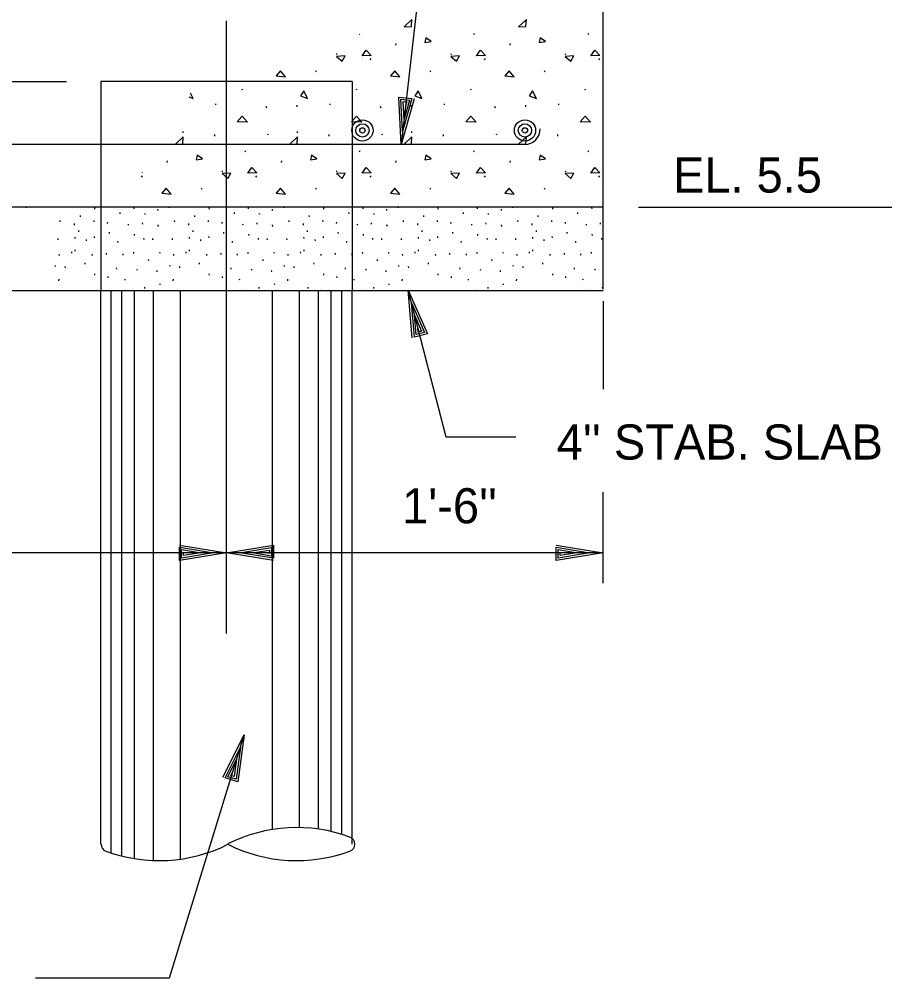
# Model space of a CAD drawing. Extents: x 0 to 320, y -4 to 473.
# Drawn here: x 13.435 to 16.911, y 11.095 to 14.916 of the extents above; entities that cross this region are included whole.
import ezdxf

# ---------------------------------------------------------------- set-up
doc = ezdxf.new("R2010")
doc.units = 0
for name, color, linetype in [('Level 10', 7, 'Continuous'), ('Level 2', 7, 'Continuous'), ('Level 3', 7, 'Continuous'), ('Level 44', 7, 'Continuous'), ('Level 50', 7, 'Continuous')]:
    doc.layers.add(name, color=color, linetype=linetype)

msp = doc.modelspace()

# ---------------------------------------------------------------- linework, layer by layer
at = {"layer": 'Level 10'}
for p, q in [((14.7906, 14.855), (14.7918, 14.8576)), ((15.2461, 14.855), (15.2484, 14.8599)), ((15.7016, 14.855), (15.7039, 14.8599)), ((14.9352, 14.813), (14.9361, 14.819)), ((15.3907, 14.813), (15.3916, 14.819)), ((14.7006, 14.775), (14.701, 14.7796)), ((14.8336, 14.7541), (14.8367, 14.7594)), ((15.1561, 14.775), (15.1565, 14.7796)), ((15.2891, 14.7541), (15.2922, 14.7594)), ((15.6116, 14.775), (15.612, 14.7796)), ((15.7446, 14.7541), (15.7478, 14.7594)), ((14.619, 14.7054), (14.6162, 14.7109)), ((15.0745, 14.7054), (15.0717, 14.7109)), ((15.5301, 14.7054), (15.5272, 14.7109)), ((14.3239, 14.6328), (14.3235, 14.6379)), ((14.7794, 14.6328), (14.779, 14.6379)), ((15.2349, 14.6328), (15.2345, 14.6379)), ((15.6905, 14.6328), (15.6901, 14.6379)), ((14.218, 14.5744), (14.2188, 14.579)), ((14.4209, 14.562), (14.4191, 14.5682)), ((14.5421, 14.567), (14.5421, 14.5732)), ((14.6735, 14.5744), (14.6743, 14.579)), ((14.8764, 14.562), (14.8746, 14.5682)), ((14.9977, 14.567), (14.9977, 14.5732)), ((15.129, 14.5744), (15.1298, 14.579)), ((15.3319, 14.562), (15.3302, 14.5682)), ((15.4532, 14.567), (15.4532, 14.5732)), ((15.5845, 14.5744), (15.5854, 14.579)), ((14.0888, 14.4633), (14.0888, 14.4691)), ((14.2141, 14.4499), (14.2141, 14.4561)), ((14.4271, 14.4541), (14.4254, 14.4586)), ((14.5443, 14.4633), (14.5443, 14.4691)), ((14.6696, 14.4499), (14.6696, 14.4561)), ((14.8827, 14.4541), (14.8809, 14.4586)), ((14.9998, 14.4633), (14.9998, 14.4691)), ((15.1252, 14.4499), (15.1252, 14.4561)), ((15.3382, 14.4541), (15.3364, 14.4586)), ((15.4554, 14.4633), (15.4554, 14.4691)), ((15.5807, 14.4499), (15.5807, 14.4561)), ((14.3351, 14.3874), (14.3373, 14.3923)), ((14.7906, 14.3874), (14.7929, 14.3923)), ((15.2461, 14.3874), (15.2484, 14.3923)), ((15.7016, 14.3874), (15.7039, 14.3923)), ((14.0241, 14.3454), (14.0251, 14.3514)), ((14.4796, 14.3454), (14.4806, 14.3514)), ((14.9352, 14.3454), (14.9361, 14.3514)), ((15.3907, 14.3454), (15.3916, 14.3514)), ((14.2451, 14.3074), (14.2455, 14.312)), ((14.7006, 14.3074), (14.701, 14.312)), ((15.1561, 14.3074), (15.1565, 14.312)), ((15.6116, 14.3074), (15.612, 14.312)), ((13.9226, 14.2865), (13.9257, 14.2918)), ((14.3781, 14.2865), (14.3812, 14.2918)), ((14.8336, 14.2865), (14.8367, 14.2918)), ((15.2891, 14.2865), (15.2922, 14.2918)), ((15.7446, 14.2865), (15.7478, 14.2918)), ((14.1635, 14.2378), (14.1607, 14.2433)), ((14.619, 14.2378), (14.6162, 14.2433)), ((15.0745, 14.2378), (15.0717, 14.2433)), ((15.5301, 14.2378), (15.5272, 14.2433)), ((13.4636, 14.1642), (13.4632, 14.1693)), ((13.7369, 14.1591), (13.7364, 14.1642)), ((13.8371, 14.1404), (13.8366, 14.1455)), ((13.8931, 14.1608), (13.8927, 14.1659)), ((13.9373, 14.1371), (13.9369, 14.1422)), ((13.9883, 14.154), (13.9879, 14.1591)), ((14.0341, 14.1642), (14.0337, 14.1693)), ((14.1928, 14.1591), (14.1924, 14.1642)), ((14.293, 14.1404), (14.2926, 14.1455)), ((14.349, 14.1608), (14.3486, 14.1659)), ((14.3932, 14.1371), (14.3928, 14.1422)), ((14.4443, 14.154), (14.4438, 14.1591)), ((14.4901, 14.1642), (14.4897, 14.1693)), ((14.6487, 14.1591), (14.6483, 14.1642)), ((14.7489, 14.1404), (14.7485, 14.1455)), ((14.805, 14.1608), (14.8046, 14.1659)), ((14.8491, 14.1371), (14.8487, 14.1422)), ((14.9002, 14.154), (14.8998, 14.1591)), ((14.946, 14.1642), (14.9456, 14.1693)), ((15.1047, 14.1591), (15.1043, 14.1642)), ((15.2049, 14.1404), (15.2045, 14.1455)), ((15.2609, 14.1608), (15.2605, 14.1659)), ((15.3051, 14.1371), (15.3047, 14.1422)), ((15.3561, 14.154), (15.3557, 14.1591)), ((15.402, 14.1642), (15.4015, 14.1693)), ((15.5606, 14.1591), (15.5602, 14.1642)), ((15.6608, 14.1404), (15.6604, 14.1455)), ((15.7169, 14.1608), (15.7164, 14.1659)), ((15.7608, 14.1395), (15.7606, 14.1422)), ((13.5986, 14.1081), (13.5982, 14.1132)), ((13.6791, 14.1285), (13.6787, 14.1336)), ((13.7334, 14.1081), (13.733, 14.1132)), ((13.7872, 14.1024), (13.788, 14.1071)), ((13.9272, 14.0997), (13.9268, 14.1048)), ((14.0546, 14.1081), (14.0541, 14.1132)), ((14.1351, 14.1285), (14.1347, 14.1336)), ((14.1894, 14.1081), (14.1889, 14.1132)), ((14.2431, 14.1024), (14.2439, 14.1071)), ((14.3831, 14.0997), (14.3827, 14.1048)), ((14.5105, 14.1081), (14.5101, 14.1132)), ((14.591, 14.1285), (14.5906, 14.1336)), ((14.6453, 14.1081), (14.6449, 14.1132)), ((14.699, 14.1024), (14.6999, 14.1071)), ((14.839, 14.0997), (14.8386, 14.1048)), ((14.9664, 14.1081), (14.966, 14.1132)), ((15.047, 14.1285), (15.0465, 14.1336)), ((15.1012, 14.1081), (15.1008, 14.1132)), ((15.155, 14.1024), (15.1558, 14.1071)), ((15.295, 14.0997), (15.2946, 14.1048)), ((15.4224, 14.1081), (15.422, 14.1132)), ((15.5029, 14.1285), (15.5025, 14.1336)), ((15.5572, 14.1081), (15.5568, 14.1132)), ((15.6109, 14.1024), (15.6118, 14.1071)), ((15.7509, 14.0997), (15.7505, 14.1048)), ((13.6554, 14.095), (13.6554, 14.1012)), ((13.6723, 14.069), (13.6719, 14.0741)), ((13.7947, 14.0623), (13.7943, 14.0674)), ((13.871, 14.0946), (13.8706, 14.0997)), ((13.9901, 14.09), (13.9883, 14.0962)), ((14.1113, 14.095), (14.1113, 14.1012)), ((14.1282, 14.069), (14.1278, 14.0741)), ((14.2506, 14.0623), (14.2502, 14.0674)), ((14.327, 14.0946), (14.3265, 14.0997)), ((14.446, 14.09), (14.4443, 14.0962)), ((14.5673, 14.095), (14.5673, 14.1012)), ((14.5841, 14.069), (14.5837, 14.0741)), ((14.7065, 14.0623), (14.7061, 14.0674)), ((14.7829, 14.0946), (14.7825, 14.0997)), ((14.902, 14.09), (14.9002, 14.0962)), ((15.0232, 14.095), (15.0232, 14.1012)), ((15.0401, 14.069), (15.0397, 14.0741)), ((15.1625, 14.0623), (15.1621, 14.0674)), ((15.2388, 14.0946), (15.2384, 14.0997)), ((15.3579, 14.09), (15.3561, 14.0962)), ((15.4791, 14.095), (15.4791, 14.1012)), ((15.496, 14.069), (15.4956, 14.0741)), ((15.6184, 14.0623), (15.618, 14.0674)), ((15.6948, 14.0946), (15.6944, 14.0997)), ((13.5901, 14.0367), (13.5897, 14.0418)), ((13.658, 14.0418), (13.6576, 14.0469)), ((13.7029, 14.0334), (13.7025, 14.0385)), ((13.7352, 14.0453), (13.7348, 14.0504)), ((13.8286, 14.0266), (13.8282, 14.0317)), ((13.8949, 14.0538), (13.8945, 14.0589)), ((13.9322, 14.0385), (13.9318, 14.0436)), ((13.9679, 14.0367), (13.9675, 14.0418)), ((14.046, 14.0367), (14.0456, 14.0418)), ((14.1139, 14.0418), (14.1135, 14.0469)), ((14.1588, 14.0334), (14.1584, 14.0385)), ((14.1911, 14.0453), (14.1907, 14.0504)), ((14.2846, 14.0266), (14.2841, 14.0317)), ((14.3508, 14.0538), (14.3504, 14.0589)), ((14.3881, 14.0385), (14.3877, 14.0436)), ((14.4238, 14.0367), (14.4234, 14.0418)), ((14.502, 14.0367), (14.5015, 14.0418)), ((14.5699, 14.0418), (14.5695, 14.0469)), ((14.6148, 14.0334), (14.6144, 14.0385)), ((14.6471, 14.0453), (14.6466, 14.0504)), ((14.7405, 14.0266), (14.7401, 14.0317)), ((14.8068, 14.0538), (14.8063, 14.0589)), ((14.844, 14.0385), (14.8436, 14.0436)), ((14.8798, 14.0367), (14.8794, 14.0418)), ((14.9579, 14.0367), (14.9575, 14.0418)), ((15.0258, 14.0418), (15.0254, 14.0469)), ((15.0707, 14.0334), (15.0703, 14.0385)), ((15.103, 14.0453), (15.1026, 14.0504)), ((15.1964, 14.0266), (15.196, 14.0317)), ((15.2627, 14.0538), (15.2623, 14.0589)), ((15.3, 14.0385), (15.2996, 14.0436)), ((15.3357, 14.0367), (15.3353, 14.0418)), ((15.4138, 14.0367), (15.4134, 14.0418)), ((15.4818, 14.0418), (15.4813, 14.0469)), ((15.5266, 14.0334), (15.5262, 14.0385)), ((15.5589, 14.0453), (15.5585, 14.0504)), ((15.6524, 14.0266), (15.652, 14.0317)), ((15.7186, 14.0538), (15.7182, 14.0589)), ((15.7559, 14.0385), (15.7555, 14.0436)), ((13.6445, 13.9841), (13.644, 13.9892)), ((13.658, 13.9913), (13.658, 13.9972)), ((13.8914, 13.9825), (13.891, 13.9876)), ((14.1004, 13.9841), (14.1, 13.9892)), ((14.1139, 13.9913), (14.1139, 13.9972)), ((14.3474, 13.9825), (14.347, 13.9876)), ((14.5563, 13.9841), (14.5559, 13.9892)), ((14.5699, 13.9913), (14.5699, 13.9972)), ((14.8033, 13.9825), (14.8029, 13.9876)), ((15.0123, 13.9841), (15.0119, 13.9892)), ((15.0258, 13.9913), (15.0258, 13.9972)), ((15.2593, 13.9825), (15.2588, 13.9876)), ((15.4682, 13.9841), (15.4678, 13.9892)), ((15.4818, 13.9913), (15.4818, 13.9972)), ((15.7152, 13.9825), (15.7148, 13.9876)), ((13.5952, 13.9739), (13.5948, 13.979)), ((13.7266, 13.9739), (13.7262, 13.979)), ((13.7833, 13.9779), (13.7833, 13.9841)), ((13.8489, 13.9756), (13.8485, 13.9807)), ((13.9509, 13.9535), (13.9505, 13.9586)), ((13.9963, 13.9822), (13.9946, 13.9866)), ((14.0511, 13.9739), (14.0507, 13.979)), ((14.1826, 13.9739), (14.1822, 13.979)), ((14.2393, 13.9779), (14.2393, 13.9841)), ((14.3049, 13.9756), (14.3045, 13.9807)), ((14.4069, 13.9535), (14.4064, 13.9586)), ((14.4523, 13.9822), (14.4505, 13.9866)), ((14.5071, 13.9739), (14.5066, 13.979)), ((14.6385, 13.9739), (14.6381, 13.979)), ((14.6952, 13.9779), (14.6952, 13.9841)), ((14.7608, 13.9756), (14.7604, 13.9807)), ((14.8628, 13.9535), (14.8624, 13.9586)), ((14.9082, 13.9822), (14.9064, 13.9866)), ((14.963, 13.9739), (14.9626, 13.979)), ((15.0945, 13.9739), (15.094, 13.979)), ((15.1511, 13.9779), (15.1511, 13.9841)), ((15.2168, 13.9756), (15.2163, 13.9807)), ((15.3187, 13.9535), (15.3183, 13.9586)), ((15.3641, 13.9822), (15.3624, 13.9866)), ((15.4189, 13.9739), (15.4185, 13.979)), ((15.5504, 13.9739), (15.55, 13.979)), ((15.6071, 13.9779), (15.6071, 13.9841)), ((15.6727, 13.9756), (15.6723, 13.9807)), ((13.5799, 13.9298), (13.5795, 13.9349)), ((13.6189, 13.9247), (13.6185, 13.9298)), ((13.6978, 13.94), (13.6974, 13.9451)), ((13.8235, 13.9196), (13.8231, 13.9247)), ((13.9043, 13.9154), (13.9065, 13.9203)), ((13.9849, 13.9093), (13.9845, 13.9144)), ((14.0358, 13.9298), (14.0354, 13.9349)), ((14.0749, 13.9247), (14.0745, 13.9298)), ((14.1537, 13.94), (14.1533, 13.9451)), ((14.2795, 13.9196), (14.279, 13.9247)), ((14.3602, 13.9154), (14.3625, 13.9203)), ((14.4408, 13.9093), (14.4404, 13.9144)), ((14.4918, 13.9298), (14.4913, 13.9349)), ((14.5308, 13.9247), (14.5304, 13.9298)), ((14.6097, 13.94), (14.6093, 13.9451)), ((14.7354, 13.9196), (14.735, 13.9247)), ((14.8161, 13.9154), (14.8184, 13.9203)), ((14.8968, 13.9093), (14.8963, 13.9144)), ((14.9477, 13.9298), (14.9473, 13.9349)), ((14.9868, 13.9247), (14.9863, 13.9298)), ((15.0656, 13.94), (15.0652, 13.9451)), ((15.1913, 13.9196), (15.1909, 13.9247)), ((15.2721, 13.9154), (15.2744, 13.9203)), ((15.3527, 13.9093), (15.3523, 13.9144)), ((15.4036, 13.9298), (15.4032, 13.9349)), ((15.4427, 13.9247), (15.4423, 13.9298)), ((15.5215, 13.94), (15.5211, 13.9451)), ((15.6473, 13.9196), (15.6469, 13.9247)), ((15.728, 13.9154), (15.7303, 13.9203)), ((13.5929, 13.8734), (13.5938, 13.8794)), ((13.7369, 13.8958), (13.7364, 13.9009)), ((13.7896, 13.8856), (13.7891, 13.8907)), ((13.8575, 13.8754), (13.8571, 13.8805)), ((14.0488, 13.8734), (14.0498, 13.8794)), ((14.1928, 13.8958), (14.1924, 13.9009)), ((14.2455, 13.8856), (14.2451, 13.8907)), ((14.3134, 13.8754), (14.313, 13.8805)), ((14.5048, 13.8734), (14.5057, 13.8794)), ((14.6487, 13.8958), (14.6483, 13.9009)), ((14.7014, 13.8856), (14.701, 13.8907)), ((14.7694, 13.8754), (14.7689, 13.8805)), ((14.9607, 13.8734), (14.9616, 13.8794)), ((15.1047, 13.8958), (15.1043, 13.9009)), ((15.1574, 13.8856), (15.157, 13.8907)), ((15.2253, 13.8754), (15.2249, 13.8805)), ((15.4166, 13.8734), (15.4176, 13.8794)), ((15.5606, 13.8958), (15.5602, 13.9009)), ((15.6133, 13.8856), (15.6129, 13.8907)), ((15.6812, 13.8754), (15.6808, 13.8805)), ((13.8859, 13.8429), (13.8859, 13.8431)), ((13.9356, 13.8431), (13.9352, 13.8482)), ((13.9968, 13.8567), (13.9963, 13.8618)), ((14.3419, 13.8429), (14.3419, 13.8431)), ((14.3915, 13.8431), (14.3911, 13.8482)), ((14.4527, 13.8567), (14.4523, 13.8618)), ((14.586, 13.8431), (14.5865, 13.8482)), ((14.6357, 13.8429), (14.6357, 13.8431)), ((14.7978, 13.8429), (14.7978, 13.8431)), ((14.8475, 13.8431), (14.8471, 13.8482)), ((14.9086, 13.8567), (14.9082, 13.8618)), ((15.2537, 13.8429), (15.2537, 13.8431)), ((15.3034, 13.8431), (15.303, 13.8482)), ((15.3646, 13.8567), (15.3641, 13.8618)), ((15.7097, 13.8429), (15.7097, 13.8431)), ((15.7594, 13.8431), (15.7589, 13.8482))]:
    msp.add_line(p, q, dxfattribs=at)
for points in [[(14.9983, 14.8875), (14.9998, 14.9153), (14.969, 14.8852)], [(15.4538, 14.8875), (15.4554, 14.9153), (15.4245, 14.8852)], [(15.0511, 14.8239), (15.0764, 14.8272), (15.0552, 14.8414)], [(15.5066, 14.8239), (15.5319, 14.8272), (15.5107, 14.8414)], [(14.8009, 14.7706), (14.8177, 14.7928), (14.8365, 14.7714)], [(15.2564, 14.7706), (15.2732, 14.7928), (15.292, 14.7714)], [(15.7119, 14.7706), (15.7287, 14.7928), (15.7476, 14.7714)], [(14.699, 14.7682), (14.7212, 14.7484), (14.7331, 14.7706)], [(15.1545, 14.7682), (15.1767, 14.7484), (15.1886, 14.7706)], [(15.6101, 14.7682), (15.6322, 14.7484), (15.6441, 14.7706)], [(14.4962, 14.6866), (14.4756, 14.7104), (14.459, 14.6907)], [(14.9517, 14.6866), (14.9311, 14.7104), (14.9145, 14.6907)], [(15.4072, 14.6866), (15.3866, 14.7104), (15.3701, 14.6907)], [(14.5557, 14.6107), (14.5841, 14.5997), (14.5691, 14.6304)], [(15.0112, 14.6107), (15.0396, 14.5997), (15.0246, 14.6304)], [(15.4667, 14.6107), (15.4952, 14.5997), (15.4802, 14.6304)], [(14.3035, 14.5077), (14.3233, 14.5291), (14.3445, 14.5054)], [(14.759, 14.5077), (14.7788, 14.5291), (14.8001, 14.5054)], [(15.2145, 14.5077), (15.2343, 14.5291), (15.2556, 14.5054)], [(15.6701, 14.5077), (15.6898, 14.5291), (15.7111, 14.5054)], [(14.0872, 14.4199), (14.0888, 14.4477), (14.058, 14.4176)], [(14.5428, 14.4199), (14.5443, 14.4477), (14.5135, 14.4176)], [(14.9983, 14.4199), (14.9998, 14.4477), (14.969, 14.4176)], [(15.4538, 14.4199), (15.4554, 14.4477), (15.4245, 14.4176)], [(14.1401, 14.3563), (14.1654, 14.3596), (14.1441, 14.3738)], [(14.5956, 14.3563), (14.6209, 14.3596), (14.5996, 14.3738)], [(15.0511, 14.3563), (15.0764, 14.3596), (15.0552, 14.3738)], [(15.5066, 14.3563), (15.5319, 14.3596), (15.5107, 14.3738)], [(14.2435, 14.3006), (14.2657, 14.2808), (14.2776, 14.303)], [(14.3454, 14.303), (14.3621, 14.3252), (14.381, 14.3038)], [(14.699, 14.3006), (14.7212, 14.2808), (14.7331, 14.303)], [(14.8009, 14.303), (14.8177, 14.3252), (14.8365, 14.3038)], [(15.1545, 14.3006), (15.1767, 14.2808), (15.1886, 14.303)], [(15.2564, 14.303), (15.2732, 14.3252), (15.292, 14.3038)], [(15.6101, 14.3006), (15.6322, 14.2808), (15.6441, 14.303)], [(15.7119, 14.303), (15.7287, 14.3252), (15.7476, 14.3038)], [(14.0407, 14.219), (14.0201, 14.2428), (14.0035, 14.2231)], [(14.4962, 14.219), (14.4756, 14.2428), (14.459, 14.2231)], [(14.9517, 14.219), (14.9311, 14.2428), (14.9145, 14.2231)], [(15.4072, 14.219), (15.3866, 14.2428), (15.3701, 14.2231)]]:
    msp.add_lwpolyline(points, close=True, dxfattribs=at)
for points in [[(14.1103, 14.6068), (14.1286, 14.5997), (14.1178, 14.6218)], [(13.9249, 14.3045), (13.9255, 14.3038), (13.9244, 14.3038)]]:
    msp.add_lwpolyline(points, dxfattribs=at)
at = {"layer": 'Level 2'}
for p, q in [((15.7608, 13.8403), (15.7608, 16.5173)), ((13.7608, 14.6673), (13.7608, 13.834)), ((14.7608, 14.6673), (13.7608, 14.6673)), ((14.7608, 14.6673), (14.7608, 13.834)), ((15.4483, 14.4173), (12.9518, 14.4173)), ((15.7608, 14.1673), (9.8858, 14.1673)), ((15.7608, 13.834), (9.2608, 13.834)), ((13.7608, 11.6278), (13.7608, 13.834)), ((13.8014, 11.5925), (13.8014, 13.834)), ((13.8436, 11.5803), (13.8436, 13.834)), ((13.8948, 11.5698), (13.8948, 13.834)), ((13.9705, 11.5625), (13.9705, 13.834)), ((14.078, 11.5682), (14.078, 13.834)), ((14.4436, 11.686), (14.4436, 13.834)), ((14.5511, 11.6936), (14.5511, 13.834)), ((14.6269, 11.6876), (14.6269, 13.834)), ((14.678, 11.6781), (14.678, 13.834)), ((14.7203, 11.6668), (14.7203, 13.834)), ((14.7608, 11.6278), (14.7608, 13.834))]:
    msp.add_line(p, q, dxfattribs=at)
for centre, radius, start, end in [((14.5406, 11.0812), 0.6125, 69.8064, 116.6071), ((14.7417, 11.6279), 0.03, 290.1936, 69.8064), ((13.7909, 11.6279), 0.03, 180, 249.6845), ((13.992, 12.1746), 0.6125, 249.8081, 296.6071), ((14.5406, 12.1746), 0.6125, 243.3929, 290.1936)]:
    msp.add_arc(centre, radius, start, end, dxfattribs=at)
at = {"layer": 'Level 3'}
for p, q in [((12.7438, 14.6673), (13.6237, 14.6673)), ((14.9624, 14.4684), (14.9624, 14.4684)), ((14.9565, 14.4167), (14.9565, 14.4167)), ((15.9025, 14.1673), (16.9113, 14.1673)), ((15.7608, 13.7916), (15.7608, 13.4409)), ((15.7608, 12.6681), (15.7608, 13.0306)), ((14.2608, 12.7892), (11.2608, 12.7892)), ((15.7608, 12.7892), (14.2608, 12.7892))]:
    msp.add_line(p, q, dxfattribs=at)
for points in [[(15.0891, 16.9624), (15.2458, 16.9624), (14.9565, 14.4167)], [(15.0084, 14.599), (14.9565, 14.4167), (14.9468, 14.606), (14.9995, 14.6), (14.9624, 14.4684), (14.9559, 14.5969), (14.9897, 14.5931), (14.968, 14.518), (14.9649, 14.5878), (14.9788, 14.5863), (14.9739, 14.5697)], [(15.4133, 13.2499), (15.1353, 13.2499), (14.9844, 13.8355)], [(13.4994, 11.0948), (14.0338, 11.0948), (14.3313, 12.0639)]]:
    msp.add_lwpolyline(points, dxfattribs=at)
msp.add_arc((15.4483, 14.4798), 0.0625, 270, 0, dxfattribs=at)
at = {"layer": 'Level 44'}
msp.add_line((14.2608, 12.4674), (14.2608, 14.9095), dxfattribs=at)
at = {"layer": 'Level 50'}
for p, q in [((14.9844, 13.8355), (14.9844, 13.8355)), ((14.9974, 13.7851), (14.9974, 13.7851)), ((14.2088, 12.7892), (14.2088, 12.7892)), ((14.2608, 12.7892), (14.2608, 12.7892)), ((14.2608, 12.7892), (14.2608, 12.7892)), ((14.3128, 12.7892), (14.3128, 12.7892)), ((15.7088, 12.7892), (15.7088, 12.7892)), ((15.7608, 12.7892), (15.7608, 12.7892)), ((14.3313, 12.0639), (14.3313, 12.0639)), ((14.316, 12.0142), (14.316, 12.0142))]:
    msp.add_line(p, q, dxfattribs=at)
for points in [[(15.0011, 13.6466), (14.9844, 13.8355), (15.0611, 13.6621), (15.0098, 13.6489), (14.9974, 13.7851), (15.0494, 13.6674), (15.0165, 13.6589), (15.0099, 13.7367), (15.0378, 13.6726), (15.0242, 13.6691), (15.0229, 13.6863)], [(14.0738, 12.8202), (14.2608, 12.7892), (14.0738, 12.7582), (14.0738, 12.8112), (14.2088, 12.7892), (14.0818, 12.7682), (14.0818, 12.8022), (14.1588, 12.7892), (14.0898, 12.7782), (14.0898, 12.7922), (14.1068, 12.7892)], [(14.4478, 12.7582), (14.2608, 12.7892), (14.4478, 12.8202), (14.4478, 12.7672), (14.3128, 12.7892), (14.4398, 12.8102), (14.4398, 12.7762), (14.3628, 12.7892), (14.4318, 12.8002), (14.4318, 12.7862), (14.4148, 12.7892)], [(15.5738, 12.8202), (15.7608, 12.7892), (15.5738, 12.7582), (15.5738, 12.8112), (15.7088, 12.7892), (15.5818, 12.7682), (15.5818, 12.8022), (15.6588, 12.7892), (15.5898, 12.7782), (15.5898, 12.7922), (15.6068, 12.7892)], [(14.2468, 11.8943), (14.3313, 12.0639), (14.306, 11.8761), (14.2554, 11.8916), (14.316, 12.0142), (14.2988, 11.8867), (14.2663, 11.8966), (14.3013, 11.9664), (14.2916, 11.8972), (14.2782, 11.9013), (14.2861, 11.9167)]]:
    msp.add_lwpolyline(points, dxfattribs=at)
for centre, radius in [((14.8023, 14.4729), 0.0422), ((14.8023, 14.4729), 0.0264), ((15.4498, 14.4729), 0.0422), ((15.4498, 14.4729), 0.0264), ((14.8023, 14.4729), 0.0105), ((15.4498, 14.4729), 0.0105)]:
    msp.add_circle(centre, radius, dxfattribs=at)

# ---------------------------------------------------------------- texts
at = {"layer": 'Level 3'}
for s, p in [('EL. 5.5', (16.0396, 14.2251)), ("4'' STAB. SLAB", (15.5764, 13.1608)), ("1'-6''", (14.9606, 12.9066))]:
    msp.add_text(s, height=0.14, dxfattribs=at).set_placement(p)

doc.saveas('drawing.dxf')
